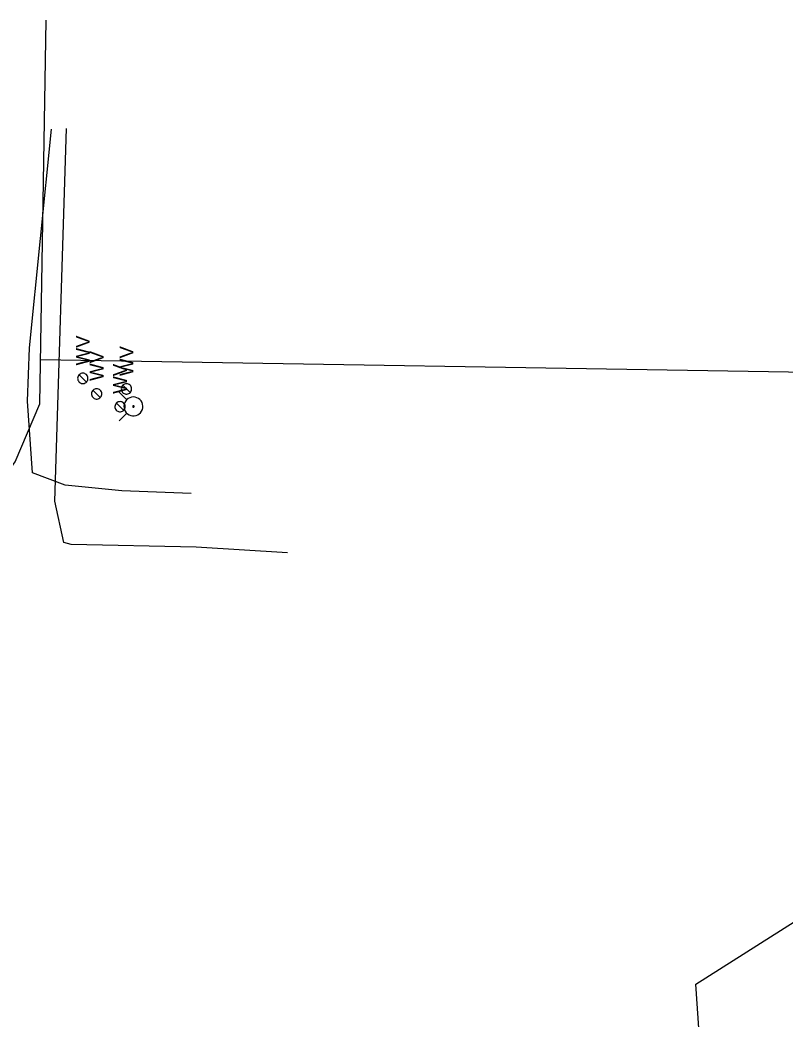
# Model space of a CAD drawing. Extents: x 596028 to 606371, y 330010 to 403088.
# Drawn here: x 604631.6 to 604843.1, y 338176.7 to 338452.9 of the extents above; entities that cross this region are included whole.
import ezdxf

# ---------------------------------------------------------------- set-up
doc = ezdxf.new("R2010")
doc.units = 0
for name, color, linetype in [('E_UTL_E_UG', 7, 'Continuous'), ('E_UTL_G_UG', 7, 'Continuous'), ('E_UTL_W', 7, 'Continuous'), ('E_UTL_WHydrant', 7, 'Continuous')]:
    doc.layers.add(name, color=color, linetype=linetype)

msp = doc.modelspace()

# ---------------------------------------------------------------- linework, layer by layer
at = {"layer": 'E_UTL_E_UG'}
for p, q in [((604637.05, 338346.84), (604638.82, 338452.87)), ((604637.25, 338359.09), (604911.55, 338354.56))]:
    msp.add_line(p, q, dxfattribs=at)
for points in [[(604678.85, 338322.09), (604659.64, 338322.8), (604643.99, 338324.36), (604635.04, 338327.77), (604633.62, 338347.59), (604634.2, 338362.29), (604640.26, 338422.74)], [(604617.83, 338316.39), (604626.08, 338325.01), (604630.22, 338330.84), (604637.05, 338346.84)], [(604825.46, 338093.49), (604823.34, 338111.37), (604818.25, 338186.57), (604849.14, 338206.21), (604870.72, 338198.67)]]:
    msp.add_lwpolyline(points, dxfattribs=at)
at = {"layer": 'E_UTL_G_UG'}
msp.add_lwpolyline([(604705.4, 338305.74), (604680.17, 338307.27), (604645.65, 338308.04), (604643.7, 338308.56), (604641.22, 338319.99), (604644.37, 338422.86)], dxfattribs=at)
at = {"layer": 'E_UTL_W'}
for points in [[(604648.9, 338355.3), (604648.63, 338355.28), (604648.37, 338355.2), (604648.13, 338355.08), (604647.92, 338354.91), (604647.74, 338354.7), (604647.61, 338354.47), (604647.52, 338354.21), (604647.48, 338353.95), (604647.49, 338353.67), (604647.56, 338353.41), (604647.67, 338353.16), (604647.83, 338352.94), (604648.02, 338352.76), (604648.25, 338352.61), (604648.5, 338352.51), (604648.77, 338352.46), (604649.04, 338352.46), (604649.31, 338352.51), (604649.56, 338352.61), (604649.79, 338352.76), (604649.98, 338352.94), (604650.14, 338353.16), (604650.25, 338353.41), (604650.31, 338353.67), (604650.33, 338353.95), (604650.29, 338354.21), (604650.2, 338354.47), (604650.07, 338354.7), (604649.89, 338354.91), (604649.67, 338355.08), (604649.43, 338355.2), (604649.17, 338355.28), (604648.9, 338355.3)], [(604649.91, 338352.87), (604647.9, 338354.89)], [(604660.97, 338352.38), (604660.7, 338352.36), (604660.44, 338352.28), (604660.2, 338352.16), (604659.98, 338351.99), (604659.81, 338351.79), (604659.67, 338351.55), (604659.58, 338351.29), (604659.54, 338351.03), (604659.56, 338350.76), (604659.62, 338350.49), (604659.73, 338350.25), (604659.89, 338350.02), (604660.09, 338349.84), (604660.31, 338349.69), (604660.57, 338349.59), (604660.83, 338349.54), (604661.1, 338349.54), (604661.37, 338349.59), (604661.62, 338349.69), (604661.85, 338349.84), (604662.05, 338350.02), (604662.2, 338350.25), (604662.32, 338350.49), (604662.38, 338350.76), (604662.39, 338351.03), (604662.35, 338351.29), (604662.26, 338351.55), (604662.13, 338351.79), (604661.95, 338351.99), (604661.74, 338352.16), (604661.5, 338352.28), (604661.24, 338352.36), (604660.97, 338352.38)], [(604661.98, 338349.95), (604659.96, 338351.97)], [(604652.72, 338351.03), (604652.45, 338351), (604652.19, 338350.93), (604651.95, 338350.8), (604651.74, 338350.63), (604651.56, 338350.43), (604651.42, 338350.19), (604651.33, 338349.94), (604651.3, 338349.67), (604651.31, 338349.4), (604651.37, 338349.14), (604651.49, 338348.89), (604651.64, 338348.67), (604651.84, 338348.48), (604652.07, 338348.33), (604652.32, 338348.23), (604652.59, 338348.18), (604652.86, 338348.18), (604653.12, 338348.23), (604653.37, 338348.33), (604653.6, 338348.48), (604653.8, 338348.67), (604653.96, 338348.89), (604654.07, 338349.14), (604654.13, 338349.4), (604654.14, 338349.67), (604654.11, 338349.94), (604654.02, 338350.19), (604653.88, 338350.43), (604653.7, 338350.63), (604653.49, 338350.8), (604653.25, 338350.93), (604652.99, 338351), (604652.72, 338351.03)], [(604653.73, 338348.59), (604651.71, 338350.61)], [(604659.19, 338347.48), (604658.92, 338347.45), (604658.66, 338347.38), (604658.42, 338347.25), (604658.2, 338347.09), (604658.03, 338346.88), (604657.89, 338346.65), (604657.8, 338346.39), (604657.76, 338346.12), (604657.78, 338345.85), (604657.84, 338345.59), (604657.95, 338345.34), (604658.11, 338345.12), (604658.31, 338344.93), (604658.53, 338344.79), (604658.79, 338344.69), (604659.05, 338344.63), (604659.32, 338344.63), (604659.59, 338344.69), (604659.84, 338344.79), (604660.07, 338344.93), (604660.27, 338345.12), (604660.42, 338345.34), (604660.54, 338345.59), (604660.6, 338345.85), (604660.61, 338346.12), (604660.57, 338346.39), (604660.48, 338346.65), (604660.35, 338346.88), (604660.17, 338347.09), (604659.96, 338347.25), (604659.72, 338347.38), (604659.46, 338347.45), (604659.19, 338347.48)], [(604660.2, 338345.05), (604658.18, 338347.06)]]:
    msp.add_lwpolyline(points, dxfattribs=at)
at = {"layer": 'E_UTL_WHydrant'}
for points in [[(604661.04, 338347.95), (604658.9, 338350.09)], [(604662.88, 338348.74), (604662.38, 338348.69), (604661.9, 338348.55), (604661.46, 338348.32), (604661.07, 338348.01), (604660.74, 338347.64), (604660.49, 338347.2), (604660.33, 338346.73), (604660.26, 338346.24), (604660.28, 338345.74), (604660.4, 338345.26), (604660.61, 338344.8), (604660.89, 338344.4), (604661.26, 338344.05), (604661.68, 338343.78), (604662.14, 338343.6), (604662.63, 338343.5), (604663.13, 338343.5), (604663.62, 338343.6), (604664.08, 338343.78), (604664.5, 338344.05), (604664.86, 338344.4), (604665.15, 338344.8), (604665.36, 338345.26), (604665.47, 338345.74), (604665.5, 338346.24), (604665.43, 338346.73), (604665.26, 338347.2), (604665.01, 338347.64), (604664.69, 338348.01), (604664.29, 338348.32), (604663.85, 338348.55), (604663.37, 338348.69), (604662.88, 338348.74)], [(604662.88, 338346.32), (604662.84, 338346.31), (604662.8, 338346.3), (604662.77, 338346.28), (604662.74, 338346.26), (604662.71, 338346.23), (604662.69, 338346.2), (604662.68, 338346.16), (604662.68, 338346.12), (604662.68, 338346.09), (604662.69, 338346.05), (604662.7, 338346.01), (604662.73, 338345.98), (604662.75, 338345.96), (604662.79, 338345.94), (604662.82, 338345.92), (604662.86, 338345.92), (604662.9, 338345.92), (604662.93, 338345.92), (604662.97, 338345.94), (604663, 338345.96), (604663.03, 338345.98), (604663.05, 338346.01), (604663.07, 338346.05), (604663.08, 338346.09), (604663.08, 338346.12), (604663.07, 338346.16), (604663.06, 338346.2), (604663.04, 338346.23), (604663.02, 338346.26), (604662.99, 338346.28), (604662.95, 338346.3), (604662.91, 338346.31), (604662.88, 338346.32)], [(604661.04, 338344.28), (604658.9, 338342.14)]]:
    msp.add_lwpolyline(points, dxfattribs=at)

# ---------------------------------------------------------------- texts
at = {"layer": 'E_UTL_W'}
for p in [(604650.83, 338357.44), (604654.65, 338353.17), (604662.89, 338354.52), (604661.11, 338349.62)]:
    msp.add_text('WV', height=3.85, rotation=90, dxfattribs=at).set_placement(p)

doc.saveas('drawing.dxf')
